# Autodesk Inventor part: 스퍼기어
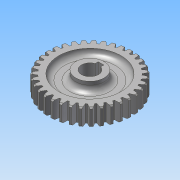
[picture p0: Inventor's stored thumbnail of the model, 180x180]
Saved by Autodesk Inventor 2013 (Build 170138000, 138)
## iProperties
Created: 2013-08
Part Number: 스퍼기어
Material: 강
Document SubType Name: Modeling
Designer: 한국산업디자인학원
Categories: <?xml version="1.0" encoding="UTF-16"?> <MemberInstance><Categories><FamilyTemplate><FamilyTemplateParameter ValueType="xs:double" Id="1" ObjectReferenceKey="da
Density: 1 g/cm^3
CustomPartVersion: 1
Author: 한국산업디자인학원
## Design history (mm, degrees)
sketch "Sketch1"
  geometry: C1 r 37 at (0, 0)
  constraints: 1 centre point
  dimensions: "d0" = 74 diameter of C1 (= da_da)
extrude "Extrusion1" new body sketch "Sketch1" distance "d1" = 15 (= da_b); taper "d2" = 0 deg
chamfer "모따기1" distance "d49" = 1; stored, may be unused: second distance "d50" = 2, angle "d51" = 45 deg
workplane "Work Plane2"
feature "피치 지름" dims "d4" = 10, "d5" = 0
workplane "Work Plane8"
workplane "Work Plane9"
feature "스퍼 기어" dims "da_b" = 15, "da_d" = 70, "da_aw" = 70, "da_da" = 74, "da_df" = 65, "da_dw" = 70, angle "da_beta" = 0 deg, "da_lefttooth" = 0, "da_righttooth" = 0
node "작업 평면11"
sketch "스케치3"
  geometry: C1 r 12.5 at (0, 0); 1 further point
  constraints: 1 centre point, 1 coincident
  dimensions: "d53" = 25 diameter of C1
extrude "돌출2" join sketch "스케치3" distance "d55" = 31; taper "d56" = 0 deg
sketch "스케치4"
  geometry: L1 (-2.5, 7.071)-(-2.5, 9.8); L2 (-2.5, 9.8)-(2.5, 9.8); L3 (2.5, 9.8)-(2.5, 7.071); C1 r 12.5 at (0, 0) reference; A1 r 7.5 centre (0, 0) between (-2.5, 7.071) and (2.5, 7.071); 1 further point
  constraints: 6 end point, 2 point on circle, 1 centre point, 1 coincident, 1 midpoint, 1 parallel, 1 perpendicular, 1 vertical, 1 vertical alignment
  dimensions: "d57" = 15 diameter of A1; "d60" = 5 distance of L1.end L2.end; "d61" = 17.3 dimension on A1 L2
extrude "돌출3" cut sketch "스케치4" stored distance "d62" = 31; taper "d63" = 0 deg
node "작업 평면12"
sketch "스케치5"
  geometry: C1 r 12.5 at (0, 0); C2 r 27.5 at (0, 0); 1 further point
  constraints: 2 centre point, 2 coincident
  dimensions: "d65" = 25 diameter of C1; "d67" = 55 diameter of C2
extrude "돌출4" cut sketch "스케치5" distance "d68" = 5; taper "d69" = 0 deg
sketch "스케치6"
  geometry: C1 r 12.5 at (0, 0) reference; C2 r 27.5 at (0, 0) reference; C3 r 12.5 at (0, 0) reference
extrude "돌출5" cut sketch "스케치6" distance "d70" = 5; taper "d71" = 0 deg
fillet "모깎기1" dims "d72" = 5
body "Solid1"
sketch "Sketch2"
  geometry: C1 r 37 at (0, 0) reference; C2 r 35 at (0, 0)
  constraints: 1 centre point, 1 coincident
  dimensions: "d3" = 70 diameter of C2 (= da_dw)
body "Srf1"
other parameters: "d17" = 0, "d34" = 0.8976 (computed from da_z), "d39" = 0, "d41" = 0, "d47" = 0, "d48" = 0, "d52" = 3, "d64" = 0
